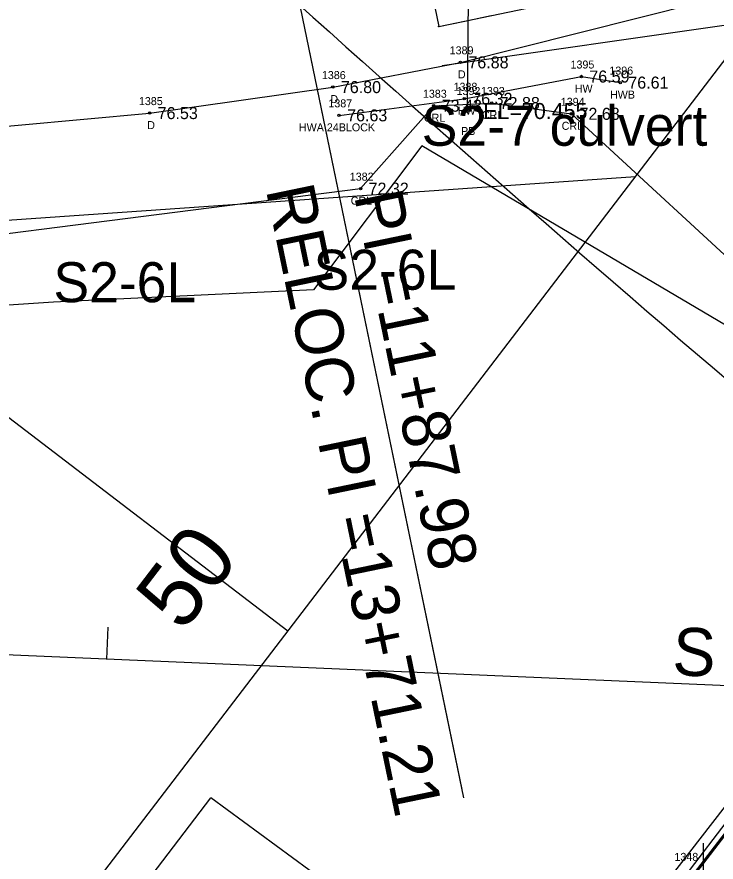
# Model space of a CAD drawing. Extents: x 2500794 to 2511032, y 910653 to 917533.
# Drawn here: x 2505953.3 to 2506040.7, y 913842.2 to 913947.8 of the extents above; entities that cross this region are included whole.
import ezdxf

# ---------------------------------------------------------------- set-up
doc = ezdxf.new("R2010")
doc.units = 0
for name, color, linetype in [('Default', 7, 'Continuous'), ('RD_EX_BldgApp', 7, 'Continuous'), ('RD_EX_Bridge', 7, 'Continuous'), ('RD_EX_Bridge_txCode', 7, 'Continuous'), ('RD_EX_DR_Pipe', 7, 'Continuous'), ('RD_EX_DR_Pipe_txCode', 7, 'Continuous'), ('RD_EX_Driveway', 7, 'Continuous'), ('RD_EX_Driveway_txCode', 7, 'Continuous'), ('RD_EX_DV_Prop', 7, 'Continuous'), ('RD_EX_GuardRail', 7, 'Continuous'), ('RD_EX_H2O', 7, 'Continuous'), ('RD_EX_H2O_txCode', 7, 'Continuous'), ('RD_EX_Misc', 7, 'Continuous'), ('RD_EX_RW', 7, 'Continuous'), ('RD_EX_TX_Bridge_ELEV', 7, 'Continuous'), ('RD_EX_TX_Driveway_ELEV', 7, 'Continuous'), ('RD_EX_TX_H2O_ELEV', 7, 'Continuous'), ('RD_EX_Wall', 7, 'Continuous'), ('RD_HC_Cl', 7, 'Continuous'), ('RD_HC_Data', 7, 'Continuous'), ('RD_HC_Data_Rel', 7, 'Continuous'), ('RD_HC_Data_Tic', 7, 'Continuous'), ('RD_HC_TX_Sta50', 7, 'Continuous'), ('RD_PD_ALT1_TnTmp', 7, 'Continuous'), ('RD_PD_BCA', 7, 'Continuous'), ('RD_PD_Bridge', 7, 'Continuous'), ('RD_PD_Signals', 7, 'Continuous'), ('RD_Sketch9', 7, 'Continuous'), ('RD_SMD_Locator', 7, 'Continuous'), ('RD_TX_Pipe_ElevEX', 7, 'Continuous')]:
    doc.layers.add(name, color=color, linetype=linetype)

# ---------------------------------------------------------------- blocks, each defined once
blk = doc.blocks.new('POINT_DISPLAY')
at = {"layer": 'Default'}
blk.add_line((0, 0), (0, 0), dxfattribs=at)
blk = doc.blocks.new('Non-Wetland Waters (Tributaries)')
at = {"layer": 'Default'}
blk.add_lwpolyline([(636545.457, 232136.839), (636535.278, 232132.59), (636524.99, 232138.661), (636521.558, 232134.094), (636513.303, 232133.696), (636494.497, 232132.445), (636478.322, 232133.569), (636463.424, 232143.109), (636451.693, 232146.366), (636448.31, 232143.99)], dxfattribs=at)

msp = doc.modelspace()

# ---------------------------------------------------------------- linework, layer by layer
at = {"layer": 'RD_EX_BldgApp'}
msp.add_line((2506016.51, 913816.53), (2506110.72, 913938.26), dxfattribs=at)
at = {"layer": 'RD_EX_Bridge'}
for points in [[(2505993.58, 913935.54), (2506009.22, 913937.61), (2506023.84, 913940.39), (2506028.71, 913939.63)], [(2506044.21, 913797.79), (2506019.43, 913816.8), (2506111, 913935.92), (2506135.82, 913916.84), (2506044.21, 913797.79)], [(2506111.24, 913935.99), (2506135.76, 913916.92), (2506044.08, 913798.01), (2506019.65, 913816.86), (2506111.24, 913935.99)]]:
    msp.add_lwpolyline(points, dxfattribs=at)
at = {"layer": 'RD_EX_DR_Pipe'}
msp.add_line((2506009.97, 913978.86), (2506009.59, 913936.08), dxfattribs=at)
at = {"layer": 'RD_EX_Driveway'}
msp.add_lwpolyline([(2505819.54, 913956.76), (2505827.1, 913947.15), (2505840.35, 913935.26), (2505856.8, 913926.65), (2505912.43, 913930.56), (2505969.91, 913935.82), (2505992.8, 913939.07), (2506008.73, 913942.16), (2506105.49, 913966.5), (2506122.82, 913958.19)], dxfattribs=at)
at = {"layer": 'RD_EX_DV_Prop'}
msp.add_line((2505758, 913909), (2506030.59, 913927.88), dxfattribs=at)
at = {"layer": 'RD_EX_GuardRail'}
msp.add_line((2506019.73, 913816.87), (2506111.18, 913935.82), dxfattribs=at)
at = {"layer": 'RD_EX_H2O_txCode'}
msp.add_lwpolyline([(2505808.2, 913925.07), (2505825.64, 913915.36), (2505914.54, 913915.98), (2505996.26, 913926.38), (2506005.4, 913936.74), (2506012.64, 913937.08), (2506022.61, 913935.73), (2506047.54, 913912.75), (2506069, 913926.42), (2506101.76, 913929.76), (2506134.82, 913911.49), (2506168.31, 913924.14), (2506205.52, 913926.29), (2506300.04, 913899.96), (2506387.24, 913834.45), (2506403.62, 913708.7), (2506351.33, 913635.45), (2506287.73, 913577.34)], dxfattribs=at)
at = {"layer": 'RD_EX_Misc'}
msp.add_line((2506039.09, 913834.62), (2506039.09, 913844.62), dxfattribs=at)
at = {"layer": 'RD_EX_RW'}
msp.add_line((2505954.67, 913828.58), (2506112.58, 914035.13), dxfattribs=at)
at = {"layer": 'RD_EX_Wall'}
msp.add_arc((2507719.02, 915869.8), 2585.05, 222.30098, 230.18686, dxfattribs=at)
at = {"layer": 'RD_HC_Cl'}
msp.add_line((2505870.76, 913871.61), (2506259.06, 913855.07), dxfattribs=at)
at = {"layer": 'RD_HC_Data'}
msp.add_line((2505988.17, 913951.65), (2506009.13, 913850.25), dxfattribs=at)
at = {"layer": 'RD_HC_Data_Rel'}
msp.add_line((2505988.17, 913951.65), (2506008.92, 913851.29), dxfattribs=at)
at = {"layer": 'RD_HC_Data_Tic'}
msp.add_line((2505964.58, 913867.61), (2505964.75, 913871.61), dxfattribs=at)
at = {"layer": 'RD_PD_ALT1_TnTmp'}
for p, q in [((2506004.4, 913954.47), (2506006.03, 913946.64)), ((2506006.03, 913946.64), (2506025.61, 913950.73))]:
    msp.add_line(p, q, dxfattribs=at)
msp.add_lwpolyline([(2506006.03, 913946.64), (2506009.29, 913947.32), (2506012.56, 913948)], dxfattribs=at)
msp.add_circle((2506006.03, 913946.64), 0.0417, dxfattribs=at)
at = {"layer": 'RD_PD_BCA'}
for p in [(2505765.19, 913572.52), (2506033.81, 913808.98)]:
    msp.add_line(p, (2505977.56, 913850.28), dxfattribs=at)
at = {"layer": 'RD_PD_Bridge'}
msp.add_line((2506007.09, 913801.65), (2506128.56, 913960.53), dxfattribs=at)
at = {"layer": 'RD_PD_Signals'}
msp.add_line((2506061.31, 913949.6), (2506006.44, 913941.72), dxfattribs=at)
at = {"layer": 'RD_Sketch9'}
msp.add_line((2505987.16, 913871.08), (2505915.82, 913925.62), dxfattribs=at)
at = {"layer": 'RD_SMD_Locator'}
for centre, radius in [((2506008.73, 913942.16), 0.15), ((2506023.84, 913940.39), 0.15), ((2506028.71, 913939.63), 0.15), ((2505992.8, 913939.07), 0.15), ((2506009.22, 913937.61), 0.15), ((2506005.4, 913936.74), 0.15), ((2506012.64, 913937.08), 0.15), ((2505969.91, 913935.82), 0.15), ((2505993.58, 913935.54), 0.15), ((2506009.59, 913936.08), 0.2), ((2506022.61, 913935.73), 0.15), ((2505996.26, 913926.38), 0.15)]:
    msp.add_circle(centre, radius, dxfattribs=at)

# ---------------------------------------------------------------- block references
at = {"layer": 'Default', "xscale": 3.937007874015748, "yscale": 3.937007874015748}
for name, p in [('Non-Wetland Waters (Tributaries)', (0, 0)), ('POINT_DISPLAY', (2506003.9, 913931.74)), ('POINT_DISPLAY', (2506003.9, 913931.74)), ('POINT_DISPLAY', (2505990.39, 913913.75)), ('POINT_DISPLAY', (2505990.39, 913913.75)), ('POINT_DISPLAY', (2505957.89, 913912.19)), ('POINT_DISPLAY', (2505957.89, 913912.19))]:
    msp.add_blockref(name, p, dxfattribs=at)
at = {"layer": 'RD_EX_H2O', "xscale": 3.937007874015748, "yscale": 3.937007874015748}
msp.add_blockref('Non-Wetland Waters (Tributaries)', (0, 0), dxfattribs=at)

# ---------------------------------------------------------------- texts
at = {"layer": 'Default'}
for s, p in [('S2-7 culvert', (2506003.9, 913931.74)), ('S2-7 culvert', (2506003.9, 913931.74)), ('S2-6L', (2505990.39, 913913.75)), ('S2-6L', (2505990.39, 913913.75)), ('S2-6L', (2505957.89, 913912.19)), ('S2-6L', (2505957.89, 913912.19))]:
    msp.add_text(s, height=5, dxfattribs=at).set_placement(p)
at = {"layer": 'RD_EX_Bridge_txCode'}
for s, p in [('1395', (2506022.49, 913941.39)), ('1396', (2506027.34, 913940.63)), ('1388', (2506007.88, 913938.61)), ('HW', (2506023.02, 913938.39)), ('HWB', (2506027.42, 913937.63)), ('1387', (2505992.24, 913936.54)), ('HW', (2506008.4, 913935.61)), ('HWA 24BLOCK', (2505988.56, 913933.54)), ('1348', (2506035.47, 913842.39))]:
    msp.add_text(s, height=1, dxfattribs=at).set_placement(p)
at = {"layer": 'RD_EX_DR_Pipe_txCode'}
for s, p in [('1392', (2506008.25, 913938.08)), ('PB', (2506008.81, 913933.08))]:
    msp.add_text(s, height=1, dxfattribs=at).set_placement(p)
at = {"layer": 'RD_EX_Driveway_txCode'}
for s, p in [('1389', (2506007.39, 913943.16)), ('1386', (2505991.43, 913940.07)), ('D', (2506008.42, 913940.16)), ('1385', (2505968.57, 913936.82)), ('D', (2505992.49, 913937.07)), ('D', (2505969.61, 913933.82))]:
    msp.add_text(s, height=1, dxfattribs=at).set_placement(p)
at = {"layer": 'RD_EX_H2O_txCode'}
for s, p in [('1383', (2506004.05, 913937.74)), ('1393', (2506011.3, 913938.08)), ('1394', (2506021.27, 913936.73)), ('CRL', (2506004.17, 913934.74)), ('CRL', (2506011.41, 913935.08)), ('CRL', (2506021.38, 913933.73)), ('1382', (2505994.91, 913927.38)), ('CRL', (2505995.03, 913924.38))]:
    msp.add_text(s, height=1, dxfattribs=at).set_placement(p)
at = {"layer": 'RD_EX_TX_Bridge_ELEV'}
for s, p in [('76.59', (2506024.84, 913939.64)), ('76.61', (2506029.71, 913938.88)), ('76.32', (2506010.22, 913936.86)), ('76.63', (2505994.58, 913934.79))]:
    msp.add_text(s, height=1.5, dxfattribs=at).set_placement(p)
at = {"layer": 'RD_EX_TX_Driveway_ELEV'}
for s, p in [('76.88', (2506009.73, 913941.41)), ('76.80', (2505993.8, 913938.32)), ('76.53', (2505970.91, 913935.07))]:
    msp.add_text(s, height=1.5, dxfattribs=at).set_placement(p)
at = {"layer": 'RD_EX_TX_H2O_ELEV'}
for s, p in [('72.88', (2506013.64, 913936.33)), ('73.43', (2506006.4, 913935.99)), ('72.68', (2506023.61, 913934.98)), ('72.32', (2505997.26, 913925.63))]:
    msp.add_text(s, height=1.5, dxfattribs=at).set_placement(p)
at = {"layer": 'RD_HC_Data'}
for s, rotation, p in [('PI =11+87.98', 281.6795, (2505995.43, 913925.53)), ('S 87%%d 33\' 42" E', 357.5616, (2506035.15, 913865.61))]:
    msp.add_text(s, height=6, rotation=rotation, dxfattribs=at).set_placement(p)
at = {"layer": 'RD_HC_Data_Rel'}
msp.add_text('RELOC. PI =13+71.21', height=6, rotation=281.6795, dxfattribs=at).set_placement((2505984.41, 913926.26))
at = {"layer": 'RD_HC_TX_Sta50'}
msp.add_text('50', height=8, rotation=52.6007, dxfattribs=at).set_placement((2505974.04, 913870.81))
at = {"layer": 'RD_TX_Pipe_ElevEX'}
msp.add_text('EL=70.455', height=2, dxfattribs=at).set_placement((2506011.59, 913935.08))

doc.saveas('drawing.dxf')
